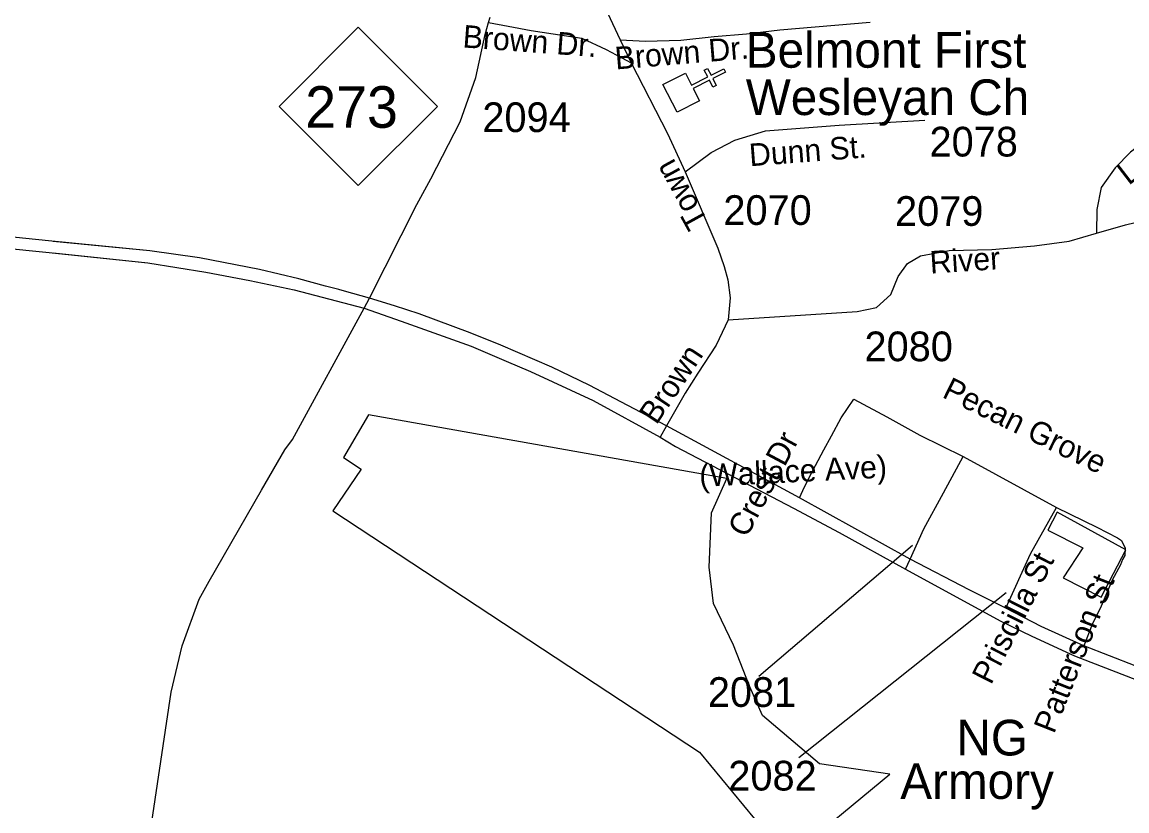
# Model space of a CAD drawing. Extents: x 1364363 to 1407445, y 538563 to 573342.
# Drawn here: x 1392969 to 1397619, y 550556 to 553876 of the extents above; entities that cross this region are included whole.
import ezdxf

# ---------------------------------------------------------------- set-up
doc = ezdxf.new("R2010")
doc.units = 0
for name, color, linetype in [('Exist Boundary Political City Limit New Hole', 7, 'Continuous'), ('Exist Cultural Armory Label', 7, 'Continuous'), ('Exist Cultural Church CELL', 7, 'Continuous'), ('Exist Cultural Church Label', 7, 'Continuous'), ('Exist Road Primary NC Attributed', 7, 'Continuous'), ('Exist Road Primary NC Divided Attributed', 7, 'Continuous'), ('Exist Road Primary NC Shield CELL', 7, 'Continuous'), ('Exist Road Primary NC Shield Number Label', 7, 'Continuous'), ('Exist Road Primary US Divided Attributed', 7, 'Continuous'), ('Exist Road Secondary Type 51 Attributed', 7, 'Continuous'), ('Exist Road Secondary Type 51 Label', 7, 'Continuous'), ('Exist Road Secondary Type 51 Number Label', 7, 'Continuous')]:
    doc.layers.add(name, color=color, linetype=linetype)

msp = doc.modelspace()

# ---------------------------------------------------------------- linework, layer by layer
at = {"layer": 'Exist Boundary Political City Limit New Hole'}
for points in [[(1394277.4, 551818.3), (1395820.5, 550803.3), (1396190.4, 550353.5), (1396621.9, 550710.7), (1396326, 550753.9), (1396085.5, 550957.6), (1396032.8, 551077.6), (1395963.2, 551252.9), (1395879.9, 551428.4), (1395861.2, 551581.3), (1395870.5, 551810.6), (1395934.8, 551955.4), (1394427.1, 552222.9), (1394322.4, 552043.9), (1394396.4, 551994.5), (1394277.4, 551818.3)], [(1394277.4, 551818.3), (1395820.5, 550803.3), (1396190.4, 550353.5), (1396621.9, 550710.7), (1396326, 550753.9), (1396085.5, 550957.6), (1396032.8, 551077.6), (1395963.2, 551252.9), (1395879.9, 551428.4), (1395861.2, 551581.3), (1395870.5, 551810.6), (1395934.8, 551955.4), (1394427.1, 552222.9), (1394322.4, 552043.9), (1394396.4, 551994.5), (1394277.4, 551818.3)], [(1397351.1, 551536.2), (1397511.6, 551454.7), (1397615.2, 551654.3), (1397326.2, 551813.8), (1397286.5, 551737.3), (1397433.6, 551662.6), (1397351.1, 551536.2)], [(1397351.1, 551536.2), (1397511.6, 551454.7), (1397615.2, 551654.3), (1397326.2, 551813.8), (1397286.5, 551737.3), (1397433.6, 551662.6), (1397351.1, 551536.2)]]:
    msp.add_lwpolyline(points, dxfattribs=at)
at = {"layer": 'Exist Cultural Church CELL'}
msp.add_lwpolyline([(1395761.1, 553661.1), (1395787.1, 553610.4), (1395854.9, 553645.1), (1395840.3, 553673.6), (1395854.5, 553680.8), (1395869.1, 553652.3), (1395922.7, 553679.7), (1395929.9, 553665.4), (1395876.4, 553638.1), (1395891, 553609.6), (1395876.7, 553602.3), (1395862.2, 553630.8), (1395794.4, 553596.1), (1395820.5, 553544.8), (1395725.7, 553496.3), (1395666.3, 553612.6)], close=True, dxfattribs=at)
msp.add_lwpolyline([(1395761.1, 553661.1), (1395787.1, 553610.4), (1395854.9, 553645.1), (1395840.3, 553673.6), (1395854.5, 553680.8), (1395869.1, 553652.3), (1395922.7, 553679.7), (1395929.9, 553665.4), (1395876.4, 553638.1), (1395891, 553609.6), (1395876.7, 553602.3), (1395862.2, 553630.8), (1395794.4, 553596.1), (1395820.5, 553544.8), (1395725.7, 553496.3), (1395666.3, 553612.6)], close=True, dxfattribs=at)
at = {"layer": 'Exist Road Primary NC Attributed'}
for points in [[(1394932.4, 553873.7), (1394939.6, 553896.5)], [(1394932.4, 553873.7), (1394939.6, 553896.5)], [(1394431.1, 552713.2), (1394630.1, 553107.7), (1394689.3, 553216.1), (1394813.1, 553455.5), (1394879.1, 553642.6), (1394917.6, 553824), (1394932.4, 553873.7)], [(1394431.1, 552713.2), (1394630.1, 553107.7), (1394689.3, 553216.1), (1394813.1, 553455.5), (1394879.1, 553642.6), (1394917.6, 553824), (1394932.4, 553873.7)], [(1393488, 549751), (1393449.5, 549962), (1393462.6, 550151.9), (1393596.8, 551055.6), (1393642.6, 551250.7), (1393714.6, 551447.1), (1393757.2, 551522.4), (1393976.4, 551905.5), (1394074.6, 552075.8), (1394107.3, 552118.3), (1394408.7, 552672.4)], [(1393488, 549751), (1393449.5, 549962), (1393462.6, 550151.9), (1393596.8, 551055.6), (1393642.6, 551250.7), (1393714.6, 551447.1), (1393757.2, 551522.4), (1393976.4, 551905.5), (1394074.6, 552075.8), (1394107.3, 552118.3), (1394408.7, 552672.4)]]:
    msp.add_lwpolyline(points, dxfattribs=at)
at = {"layer": 'Exist Road Primary NC Divided Attributed'}
msp.add_lwpolyline([(1394408.7, 552672.4), (1394431.1, 552713.2)], dxfattribs=at)
msp.add_lwpolyline([(1394408.7, 552672.4), (1394431.1, 552713.2)], dxfattribs=at)
at = {"layer": 'Exist Road Primary NC Shield CELL'}
msp.add_lwpolyline([(1394051.4, 553520.8), (1394384.4, 553853.8), (1394717.4, 553520.8), (1394384.4, 553187.8)], close=True, dxfattribs=at)
at = {"layer": 'Exist Road Primary US Divided Attributed'}
msp.add_line((1396240.9, 551872.9), (1395680.9, 552175.9), dxfattribs=at)
msp.add_line((1396240.9, 551872.9), (1395680.9, 552175.9), dxfattribs=at)
for points in [[(1394431.1, 552713.2), (1394325.9, 552743.1), (1394302, 552751), (1394245.7, 552764.1), (1394133.9, 552794.7), (1393968.9, 552834.1), (1393716.2, 552883), (1393507, 552912.9), (1393079.7, 552955), (1392438.5, 553021.5), (1392109.8, 553055.5), (1391491.7, 553120.7), (1391063.1, 553158.7), (1390486.4, 553185.9), (1390198.3, 553176.8)], [(1390201.7, 553130.5), (1390497.3, 553127.5), (1391040, 553112.6), (1391494.4, 553066.4), (1392107.1, 553003.9), (1393068.9, 552907.4), (1393498.8, 552862.6), (1393742, 552823.2), (1393928.1, 552787.9), (1394114.9, 552748.5), (1394408.7, 552672.4)], [(1394431.1, 552713.2), (1394325.9, 552743.1), (1394302, 552751), (1394245.7, 552764.1), (1394133.9, 552794.7), (1393968.9, 552834.1), (1393716.2, 552883), (1393507, 552912.9), (1393099.7, 552953)], [(1393099.7, 552904.2), (1393498.8, 552862.6), (1393742, 552823.2), (1393928.1, 552787.9), (1394114.9, 552748.5), (1394408.7, 552672.4)], [(1395680.9, 552175.9), (1395355.5, 552347.7), (1395198.6, 552423.2), (1394983.8, 552516.6), (1394855.3, 552567.7), (1394640.3, 552648), (1394537, 552681.9), (1394431.1, 552713.2)], [(1395680.9, 552175.9), (1395355.5, 552347.7), (1395198.6, 552423.2), (1394983.8, 552516.6), (1394855.3, 552567.7), (1394640.3, 552648), (1394537, 552681.9), (1394431.1, 552713.2)], [(1394408.7, 552672.4), (1394564.7, 552617), (1394858.7, 552511.4), (1395006.1, 552448.3), (1395109.3, 552405.5), (1395372.2, 552282.5), (1395654.4, 552129)], [(1394408.7, 552672.4), (1394564.7, 552617), (1394858.7, 552511.4), (1395006.1, 552448.3), (1395109.3, 552405.5), (1395372.2, 552282.5), (1395654.4, 552129)], [(1395654.4, 552129), (1395719.8, 552090.2), (1396216.1, 551829.5), (1396408, 551726.9), (1396688, 551572.7)], [(1395654.4, 552129), (1395719.8, 552090.2), (1396216.1, 551829.5), (1396408, 551726.9), (1396688, 551572.7)], [(1396707.3, 551615.5), (1396240.9, 551872.9)], [(1396707.3, 551615.5), (1396240.9, 551872.9)], [(1397109.3, 551408.9), (1396955.7, 551485.8), (1396707.3, 551615.5)], [(1397109.3, 551408.9), (1396955.7, 551485.8), (1396707.3, 551615.5)], [(1396688, 551572.7), (1397085.3, 551356.4), (1397219.1, 551291.3), (1397398.7, 551208.4), (1397641.9, 551114.2), (1397789.9, 551058.5), (1398037.5, 550977), (1398247.1, 550917.9), (1398569.4, 550837.8), (1398746.2, 550797.8)], [(1396688, 551572.7), (1397085.3, 551356.4), (1397219.1, 551291.3), (1397398.7, 551208.4), (1397641.9, 551114.2), (1397789.9, 551058.5), (1398037.5, 550977), (1398247.1, 550917.9), (1398569.4, 550837.8), (1398746.2, 550797.8)], [(1397438.1, 551250.1), (1397257.9, 551331.8), (1397109.3, 551408.9)], [(1397438.1, 551250.1), (1397257.9, 551331.8), (1397109.3, 551408.9)], [(1398753.1, 550836.4), (1398606.7, 550879.2), (1398317.7, 550951.2), (1398057.9, 551025.9), (1397867.4, 551085), (1397654, 551166.1), (1397438.1, 551250.1)], [(1398753.1, 550836.4), (1398606.7, 550879.2), (1398317.7, 550951.2), (1398057.9, 551025.9), (1397867.4, 551085), (1397654, 551166.1), (1397438.1, 551250.1)]]:
    msp.add_lwpolyline(points, dxfattribs=at)
at = {"layer": 'Exist Road Secondary Type 51 Attributed'}
for p, q in [((1395487.1, 553801.3), (1395533.1, 553704.3)), ((1395487.1, 553801.3), (1395533.1, 553704.3)), ((1396929.7, 552048), (1397322.9, 551833.4)), ((1396929.7, 552048), (1397322.9, 551833.4))]:
    msp.add_line(p, q, dxfattribs=at)
for points in [[(1395316.5, 554165.1), (1395487.1, 553801.3)], [(1395316.5, 554165.1), (1395487.1, 553801.3)], [(1395487.1, 553801.3), (1395593, 553795.1), (1395741.2, 553799.9), (1395881.5, 553815.1), (1396017.8, 553826.4), (1396158.2, 553843.4), (1396539.1, 553875.8)], [(1395487.1, 553801.3), (1395593, 553795.1), (1395741.2, 553799.9), (1395881.5, 553815.1), (1396017.8, 553826.4), (1396158.2, 553843.4), (1396539.1, 553875.8)], [(1394932.4, 553873.7), (1395014.8, 553858.7), (1395111.7, 553841), (1395325.1, 553808.7), (1395428.2, 553760.4), (1395533.1, 553704.3)], [(1394932.4, 553873.7), (1395014.8, 553858.7), (1395111.7, 553841), (1395325.1, 553808.7), (1395428.2, 553760.4), (1395533.1, 553704.3)], [(1395533.1, 553704.3), (1395685, 553407.1), (1395759.6, 553245.3)], [(1395533.1, 553704.3), (1395685, 553407.1), (1395759.6, 553245.3)], [(1398019, 553504.7), (1397875.6, 553452.1), (1397705.8, 553383.3), (1397634.9, 553328.8), (1397570.1, 553262.4), (1397511.1, 553179), (1397493.3, 553087.3), (1397491.3, 552987.3)], [(1398019, 553504.7), (1397875.6, 553452.1), (1397705.8, 553383.3), (1397634.9, 553328.8), (1397570.1, 553262.4), (1397511.1, 553179), (1397493.3, 553087.3), (1397491.3, 552987.3)], [(1395759.6, 553245.3), (1395869.5, 553327.1), (1395968.6, 553379.2), (1396097.5, 553418.4), (1396408.1, 553441.9), (1396768.3, 553462.8)], [(1395759.6, 553245.3), (1395869.5, 553327.1), (1395968.6, 553379.2), (1396097.5, 553418.4), (1396408.1, 553441.9), (1396768.3, 553462.8)], [(1397491.3, 552987.3), (1397614, 553022.7), (1397829.2, 553074.4), (1398089.4, 553108.3), (1398226.3, 553120.2), (1398579.5, 553168.7), (1398693.9, 553186.4), (1398746.8, 553188.9), (1398781, 553210.3), (1398807.8, 553243.4), (1398812.7, 553314.1), (1398803.1, 553334.3)], [(1397491.3, 552987.3), (1397614, 553022.7), (1397829.2, 553074.4), (1398089.4, 553108.3), (1398226.3, 553120.2), (1398579.5, 553168.7), (1398693.9, 553186.4), (1398746.8, 553188.9), (1398781, 553210.3), (1398807.8, 553243.4), (1398812.7, 553314.1), (1398803.1, 553334.3)], [(1395759.6, 553245.3), (1395897, 552924.4), (1395923.5, 552847.8), (1395940.2, 552791), (1395949.6, 552714.9), (1395940.8, 552622.3)], [(1395759.6, 553245.3), (1395897, 552924.4), (1395923.5, 552847.8), (1395940.2, 552791), (1395949.6, 552714.9), (1395940.8, 552622.3)], [(1395940.8, 552622.3), (1396483.9, 552658), (1396565.9, 552675.2), (1396625.4, 552729), (1396657, 552804.4), (1396696.1, 552859.7), (1396750.8, 552892.6), (1396871.3, 552914.2), (1397051.5, 552918.3), (1397230.1, 552934.8), (1397376.3, 552953.6), (1397491.3, 552987.3)], [(1395940.8, 552622.3), (1396483.9, 552658), (1396565.9, 552675.2), (1396625.4, 552729), (1396657, 552804.4), (1396696.1, 552859.7), (1396750.8, 552892.6), (1396871.3, 552914.2), (1397051.5, 552918.3), (1397230.1, 552934.8), (1397376.3, 552953.6), (1397491.3, 552987.3)], [(1395940.8, 552622.3), (1395890.6, 552516.6), (1395813.1, 552398.5), (1395760.3, 552313.9), (1395680.9, 552175.9)], [(1395940.8, 552622.3), (1395890.6, 552516.6), (1395813.1, 552398.5), (1395760.3, 552313.9), (1395680.9, 552175.9)], [(1396240.9, 551872.9), (1396256, 551904.8), (1396284.1, 551964.7), (1396343.1, 552075.7), (1396376.6, 552133.9), (1396416.2, 552209.6), (1396469.9, 552288.9), (1396609, 552214.9), (1396748.1, 552137.4), (1396929.7, 552048)], [(1396240.9, 551872.9), (1396256, 551904.8), (1396284.1, 551964.7), (1396343.1, 552075.7), (1396376.6, 552133.9), (1396416.2, 552209.6), (1396469.9, 552288.9), (1396609, 552214.9), (1396748.1, 552137.4), (1396929.7, 552048)], [(1395680.9, 552175.9), (1395654.4, 552129)], [(1395680.9, 552175.9), (1395654.4, 552129)], [(1396707.3, 551615.5), (1396764.8, 551743), (1396847.6, 551894.2), (1396929.7, 552048)], [(1396707.3, 551615.5), (1396764.8, 551743), (1396847.6, 551894.2), (1396929.7, 552048)], [(1397109.3, 551408.9), (1397213.8, 551637.3), (1397322.9, 551833.4)], [(1397109.3, 551408.9), (1397213.8, 551637.3), (1397322.9, 551833.4)], [(1397322.9, 551833.4), (1397493.4, 551750.6), (1397580.3, 551704.8), (1397596.1, 551694.5), (1397611.8, 551661.3), (1397610, 551631.3), (1397601.2, 551613.7), (1397592.4, 551590.8), (1397557.2, 551527.4), (1397511.4, 551418.1), (1397472.7, 551340.6), (1397438.1, 551250.1)], [(1397322.9, 551833.4), (1397493.4, 551750.6), (1397580.3, 551704.8), (1397596.1, 551694.5), (1397611.8, 551661.3), (1397610, 551631.3), (1397601.2, 551613.7), (1397592.4, 551590.8), (1397557.2, 551527.4), (1397511.4, 551418.1), (1397472.7, 551340.6), (1397438.1, 551250.1)], [(1396688, 551572.7), (1396707.3, 551615.5)], [(1396688, 551572.7), (1396707.3, 551615.5)]]:
    msp.add_lwpolyline(points, dxfattribs=at)
at = {"layer": 'Exist Road Secondary Type 51 Number Label'}
for p, q in [((1396717.5, 551673.4), (1396070.7, 551121.2)), ((1396717.5, 551673.4), (1396070.7, 551121.2)), ((1397111.8, 551473.6), (1396239, 550779.5)), ((1397111.8, 551473.6), (1396239, 550779.5))]:
    msp.add_line(p, q, dxfattribs=at)

# ---------------------------------------------------------------- texts
at = {"layer": 'Exist Cultural Armory Label'}
for s, p in [('NG ', (1396901.8, 550789.1)), ('NG ', (1396901.8, 550789.1)), ('Armory', (1396665.5, 550606.3)), ('Armory', (1396665.5, 550606.3))]:
    msp.add_text(s, height=150, dxfattribs=at).set_placement(p)
at = {"layer": 'Exist Cultural Church Label'}
for s, p in [('Belmont First', (1396015.2, 553683.8)), ('Belmont First', (1396015.2, 553683.8)), ('Wesleyan Ch', (1396015.2, 553484.6)), ('Wesleyan Ch', (1396015.2, 553484.6))]:
    msp.add_text(s, height=150, dxfattribs=at).set_placement(p)
at = {"layer": 'Exist Road Primary NC Shield Number Label'}
msp.add_text('273', height=175, dxfattribs=at).set_placement((1394160.6, 553431.1))
at = {"layer": 'Exist Road Secondary Type 51 Label'}
for s, rotation, p in [('Brown Dr.', 355.8371, (1394821.6, 553769.4)), ('Brown Dr.', 355.8371, (1394821.6, 553769.4)), ('Brown Dr.', 4.7241, (1395468, 553676.2)), ('Brown Dr.', 4.7241, (1395468, 553676.2)), ('Dunn St.', 4.3375, (1396032.7, 553268.8)), ('Dunn St.', 4.3375, (1396032.7, 553268.8)), ('Loop', 37.5804, (1397626.7, 553186.4)), ('Loop', 37.5804, (1397626.7, 553186.4)), ('Town', 118.8633, (1395859, 553035.3)), ('Town', 118.8633, (1395859, 553035.3)), ('River ', 3.7642, (1396792.5, 552816.8)), ('River ', 3.7642, (1396792.5, 552816.8)), ('Brown', 56.178, (1395639.3, 552177.4)), ('Brown', 56.178, (1395639.3, 552177.4)), ('Pecan Grove', 333.7875, (1396837.5, 552299.1)), ('Pecan Grove', 333.7875, (1396837.5, 552299.1)), ('Crest Dr', 61.9284, (1396018.8, 551701.5)), ('Crest Dr', 61.9284, (1396018.8, 551701.5)), ('(Wallace Ave)', 2.8897, (1395821.5, 551919)), ('(Wallace Ave)', 2.8897, (1395821.5, 551919)), ('Priscilla St', 63.1023, (1397047.3, 551083)), ('Priscilla St', 63.1023, (1397047.3, 551083)), ('Patterson St', 68.4931, (1397312.7, 550876.7)), ('Patterson St', 68.4931, (1397312.7, 550876.7))]:
    msp.add_text(s, height=95, rotation=rotation, dxfattribs=at).set_placement(p)
at = {"layer": 'Exist Road Secondary Type 51 Number Label'}
for s, p in [('2094', (1394906.5, 553412.9)), ('2094', (1394906.5, 553412.9)), ('2078', (1396788.6, 553310.1)), ('2078', (1396788.6, 553310.1)), ('2070', (1395920.9, 553022.1)), ('2070', (1395920.9, 553022.1)), ('2079', (1396643.4, 553018.1)), ('2079', (1396643.4, 553018.1)), ('2080', (1396514.9, 552448.4)), ('2080', (1396514.9, 552448.4)), ('2081', (1395855.6, 550993.5)), ('2081', (1395855.6, 550993.5)), ('2082', (1395941.8, 550641.5)), ('2082', (1395941.8, 550641.5))]:
    msp.add_text(s, height=125, dxfattribs=at).set_placement(p)

doc.saveas('drawing.dxf')
